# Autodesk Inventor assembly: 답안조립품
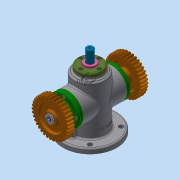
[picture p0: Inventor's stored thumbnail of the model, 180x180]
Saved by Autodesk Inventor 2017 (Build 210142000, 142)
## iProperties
Part Number: 답안조립품
Material: 일반
Document SubType Name: Assembly
Designer: mrc
Mass: 1861.33 g
Surface Area: 1735.34 cm^2
Volume: 520.939 cm^3
Density: 3.57302 g/cm^3
Author: mrc
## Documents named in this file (17)
- C:\Users\mrc\Desktop\600606V1014\답안조립품.iam
- C:\Users\mrc\Desktop\600606V1014\본체.ipt
- C:\Users\mrc\Desktop\600606V1014\가변스프링.ipt
- C:\Users\mrc\Desktop\600606V1014\멈춤링.ipt
- C:\Users\mrc\Desktop\600606V1014\베어링 6203.ipt
- C:\Users\mrc\Desktop\600606V1014\볼트 M4.ipt
- C:\Users\mrc\Desktop\600606V1014\부시.ipt
- C:\Users\mrc\Desktop\600606V1014\스퍼기어.ipt
- C:\Users\mrc\Desktop\600606V1014\스프링와셔.ipt
- C:\Users\mrc\Desktop\600606V1014\스프링조립용 와셔.ipt
- C:\Users\mrc\Desktop\600606V1014\슬라이더.ipt
- C:\Users\mrc\Desktop\600606V1014\오일 실 17 30 8.ipt
- C:\Users\mrc\Desktop\600606V1014\커버 A.ipt
- C:\Users\mrc\Desktop\600606V1014\커버 B.ipt
- C:\Users\mrc\Desktop\600606V1014\키 4x4x12.ipt
- C:\Users\mrc\Desktop\600606V1014\편심축.ipt
- C:\Users\mrc\Desktop\600606V1014\평와셔.ipt
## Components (1 placed, 1 different names)
1. 가변스프링:1
